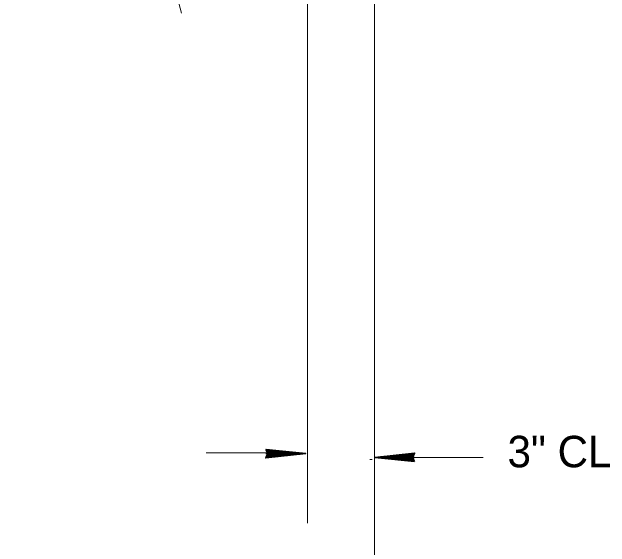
# Model space of a CAD drawing. Extents: x 3.64 to 6.84, y -0.8 to 1.19.
# Drawn here: x 4.5985 to 4.7568, y -0.376 to -0.2344 of the extents above; entities that cross this region are included whole.
import ezdxf

# ---------------------------------------------------------------- set-up
doc = ezdxf.new("R2010")
doc.units = 0
doc.header["$LTSCALE"] = 0.0033
doc.linetypes.add('DOT_DASHED', pattern=[7.7, 5, -1.2, 0.3, -1.2])
doc.linetypes.add('MEDIUM_DASHED', pattern=[4.5, 3, -1.5])
doc.layers.add('1', color=7, linetype='Continuous', lineweight=40)
doc.layers.add('5', color=7, linetype='MEDIUM_DASHED', lineweight=13)

msp = doc.modelspace()

# ---------------------------------------------------------------- linework, layer by layer
at = {"layer": '1', "lineweight": 13}
for p, q in [((4.67675, -0.123583), (4.67675, -0.36975)), ((4.694417, -0.22875), (4.694417, -0.413667)), ((4.649917, -0.351083), (4.67075, -0.351083)), ((4.69325, -0.352833), (4.693833, -0.352833)), ((4.702417, -0.352333), (4.72325, -0.352333))]:
    msp.add_line(p, q, dxfattribs=at)
at = {"layer": '1', "lineweight": 35}
for p, q in [((4.665667, -0.35125), (4.67625, -0.35125)), ((4.665833, -0.351917), (4.673167, -0.351167)), ((4.665917, -0.35025), (4.67375, -0.351167)), ((4.665917, -0.35025), (4.67375, -0.351167)), ((4.665917, -0.350333), (4.67375, -0.351167)), ((4.665917, -0.350417), (4.67375, -0.35125)), ((4.665917, -0.350417), (4.67375, -0.351417)), ((4.665917, -0.352083), (4.67325, -0.35125)), ((4.704833, -0.35125), (4.6975, -0.352083)), ((4.665917, -0.352167), (4.67325, -0.351417)), ((4.665917, -0.352333), (4.67325, -0.3515)), ((4.705083, -0.352333), (4.6945, -0.352333)), ((4.704833, -0.353167), (4.697, -0.352167)), ((4.704833, -0.353167), (4.697, -0.352333)), ((4.704833, -0.353333), (4.697, -0.352417)), ((4.704833, -0.353333), (4.697, -0.352417)), ((4.704833, -0.35325), (4.697, -0.352417)), ((4.704833, -0.351417), (4.6975, -0.352167)), ((4.704833, -0.3515), (4.6975, -0.352333)), ((4.704917, -0.351667), (4.697583, -0.352417))]:
    msp.add_line(p, q, dxfattribs=at)
for points in [[(4.665667, -0.350167), (4.67625, -0.35125), (4.665667, -0.352417), (4.66625, -0.35125)], [(4.666417, -0.351167), (4.671083, -0.351083), (4.671083, -0.351167), (4.670167, -0.351167), (4.666417, -0.351083), (4.669417, -0.351), (4.66625, -0.350917), (4.6685, -0.350833), (4.66625, -0.35075), (4.66975, -0.351), (4.674417, -0.351167), (4.6735, -0.351417), (4.67475, -0.351417), (4.666417, -0.351417), (4.668833, -0.351583), (4.66625, -0.351583), (4.671583, -0.351167), (4.66625, -0.351833)], [(4.705083, -0.353417), (4.6945, -0.352333), (4.705083, -0.351167), (4.7045, -0.352333)], [(4.704333, -0.352417), (4.699667, -0.3525), (4.699667, -0.352417), (4.700583, -0.352417), (4.704333, -0.3525), (4.701333, -0.352583), (4.7045, -0.352667), (4.70225, -0.35275), (4.7045, -0.352833), (4.701, -0.352583), (4.696333, -0.352417), (4.69725, -0.352167), (4.696, -0.352167), (4.704333, -0.352167), (4.701917, -0.352), (4.7045, -0.352), (4.699167, -0.352417), (4.7045, -0.35175)]]:
    msp.add_lwpolyline(points, close=True, dxfattribs=at)
for points in [[(4.666417, -0.351167), (4.666, -0.350417), (4.66625, -0.350667), (4.666417, -0.351), (4.666667, -0.350917), (4.6665, -0.350583), (4.666333, -0.351333), (4.666167, -0.351833), (4.665917, -0.35225)], [(4.704333, -0.352417), (4.70475, -0.353167), (4.7045, -0.352917), (4.704333, -0.352583), (4.704083, -0.352667), (4.70425, -0.353), (4.704417, -0.35225), (4.704583, -0.35175), (4.704833, -0.351333)]]:
    msp.add_lwpolyline(points, dxfattribs=at)
at = {"layer": '5', "linetype": 'DOT_DASHED'}
msp.add_lwpolyline([(4.5985, -0.055083), (4.619083, -0.137667), (4.648417, -0.255)], dxfattribs=at)

# ---------------------------------------------------------------- texts
at = {"layer": '1'}
msp.add_text('3" CL', height=0.008334, dxfattribs=at).set_placement((4.729667, -0.354917))

doc.saveas('drawing.dxf')
